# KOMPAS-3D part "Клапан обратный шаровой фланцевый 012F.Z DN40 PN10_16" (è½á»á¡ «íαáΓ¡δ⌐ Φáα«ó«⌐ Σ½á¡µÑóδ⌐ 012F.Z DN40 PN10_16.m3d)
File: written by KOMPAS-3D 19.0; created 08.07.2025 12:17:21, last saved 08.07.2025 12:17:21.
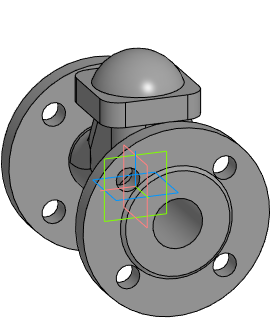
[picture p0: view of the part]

Document properties: Полное имя файла: E:\Dendor Работа Сачек\3D для проектировщиков\5.3 Тип 012F, 012F.Z Клапан обратный шаровой фланцевый\stp_Клапан обратный шаровой фланцевый 012F.Z PN10_16\Клапан обратный шаровой фланцевый 012F.Z DN40 PN10_16.m3d

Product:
- Part/product: Клапан обратный шаровой фланцевый 012F.Z DN40 PN10_16

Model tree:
1. Операция без истории:1  (labels: Клапан обратный шаровой фланцевый 012F.Z DN40 PN10_16)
